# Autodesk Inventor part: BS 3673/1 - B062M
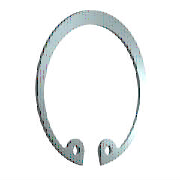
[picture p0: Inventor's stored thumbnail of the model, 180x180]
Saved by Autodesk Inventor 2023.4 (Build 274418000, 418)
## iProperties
Created: 2022-02
Part Number: BS 3673/1 - B062M
Material: Acier, doux
Description: Spécifications des anneaux élastiques - Anneaux élastiques en acier au carbone
Document SubType Name: Modeling
Standard: BS 3673/1
Designer: bruno
Standards Organization: BSI
Language: fr-FR
Size Designation: B062M
Categories: <MemberInstance><Categories><Category DisplayName="Pièces d'arbre" InternalName="7f7aeb1f-a693-4053-b835-cee3144e0d98" Mnemonic="SHFT"><Category DisplayName="An
Density: 7.85 g/cm^3
Appearance: Semi-poli
IsCustomPart: 0
Author: bruno
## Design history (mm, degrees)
sketch "Esquisse1"
  geometry: L1 (0, 15.113)-(0, -73.177) reference; L2 (-45.5, 0)-(45.5, 0) reference; L3 (-4.964, 2.449)-(1.502, 2.449); L4 (0, -2.835)-(-5.307, -2.835); L5 (0, -30)-(-13.341, -59.579); L6 (-13.341, -59.579)-(-26.912, -53.458); L7 (-11.268, -54.983)-(-21.82, -50.224); L8 (-8.999, -56.007)-(-11.032, -60.515); L9 (8.999, -56.007)-(11.032, -60.515); C1 r 1.245 at (-11.268, -54.983); C2 r 1.245 at (11.268, -54.983); A1 r 28.486 centre (0, -31.321) between (16.904, -54.25) and (-16.904, -54.25); A2 r 32.449 centre (0, -30) between (11.032, -60.515) and (-11.032, -60.515); A3 r 2.489 centre (-11.268, -54.983) between (-8.999, -56.007) and (-13.347, -53.615); A4 r 2.489 centre (-15.426, -52.246) between (-16.904, -54.25) and (-13.347, -53.615); A5 r 2.489 centre (15.426, -52.246) between (13.347, -53.615) and (16.904, -54.25); A6 r 2.489 centre (11.268, -54.983) between (13.347, -53.615) and (8.999, -56.007); 3 further points
  constraints: 15 point on circle, 14 end point, 9 symmetric about line, 8 centre point, 6 tangent, 4 coincident, 4 point on line, 3 perpendicular, 1 parallel, 4 other
  dimensions: "d8" = 1.3208 distance of A1.centre L5.start (= 0.25 x SRB1); "d38" = 5.2832 distance between parallel lines of L4 L3 (= SRB1); "d39" = 30 distance from line of L5.start L2 (= 0.5 x WD); "d43" = 32.4485 radius of A2 (= 0.5 x ND); "d45" = 5.0419 distance between parallel lines of L7 L6 (= 0.5 x SRB2); "d46" = 2.4892 radius of A4 (= SD5); "d47" = 11.03249 distance from line of L1 L8.end (= 0.17 x ND); "d48" = 2.4892 diameter of C1 (= SD5); "d49" = 2.4892 radius of A3 (= SD5)
extrude "Corps" new body sketch "Esquisse1" distance "d2" = 2.032 (= SD); taper "d3" = 0 deg
workaxis "Work Axis1"
workaxis "Work Axis2"
workplane "Work Plane1"
body "Solid1"
other parameters: "SD" = 2.032 [user parameter; used in 1 equation term], "SRB1" = 5.2832 [user parameter; used in 2 equation terms], "ND" = 64.897 [user parameter; used in 3 equation terms], "SRB2" = 10.0838 [user parameter; used in 1 equation term], "SD5" = 2.4892 [user parameter; used in 3 equation terms], "d50" = 0, "d51" = 0, "d52" = 0, "d53" = 0, "SD3" = 64.897 (= ND) [user parameter], "NND" = 62 [user parameter; used in 1 equation term], "WDMAX" = 62 (= NND) [user parameter]
